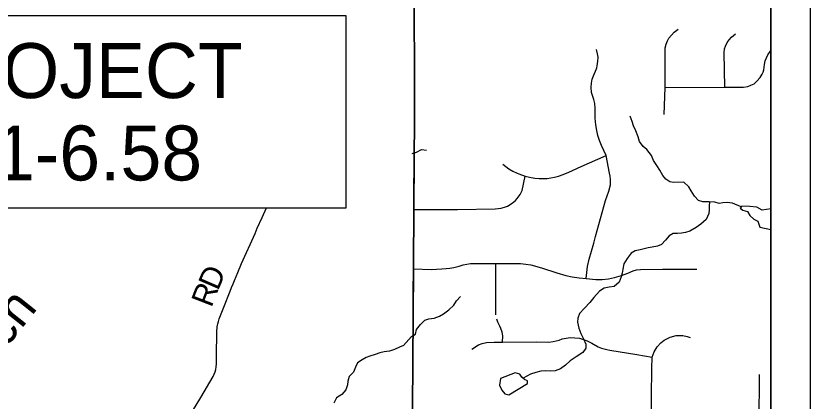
# Model space of a CAD drawing. Extents: x 0 to 34, y 0 to 22.
# Drawn here: x 6.974 to 9, y 17.051 to 18.033 of the extents above; entities that cross this region are included whole.
import ezdxf

# ---------------------------------------------------------------- set-up
doc = ezdxf.new("R2010")
doc.units = 0
for name, color, linetype in [('GM_X_Corporation', 7, 'Continuous'), ('GM_X_County_Road', 7, 'Continuous'), ('GM_X_Minor_Lake', 7, 'Continuous'), ('GM_X_Minor_River', 7, 'Continuous'), ('GM_X_Minor_River_Text', 7, 'Continuous'), ('GM_X_Township_Road', 7, 'Continuous'), ('GM_X_Township_Road_Text', 7, 'Continuous'), ('SH_Data', 7, 'Continuous'), ('SH_Text', 7, 'Continuous')]:
    doc.layers.add(name, color=color, linetype=linetype)

msp = doc.modelspace()

# ---------------------------------------------------------------- linework, layer by layer
at = {"layer": 'GM_X_Corporation'}
for points in [[(2.1, 20.9), (2.1, 14.1), (7.9734, 14.1), (7.9726, 14.5453), (7.9765, 15.2637), (7.9792, 15.5481), (7.979, 15.5988), (7.9808, 15.7192), (7.9807, 15.9078), (7.9821, 16.2487), (7.9825, 16.3395), (7.9818, 16.3982), (7.9825, 16.6077), (7.9838, 16.7968), (7.9877, 17.3871), (7.9891, 17.5498), (7.991, 17.7727), (7.9901, 18.1613)], [(7.9901, 18.1613), (7.991, 17.7727), (7.9891, 17.5498), (7.9877, 17.3871), (7.9838, 16.7968), (7.9825, 16.6077), (7.9818, 16.3982), (7.9825, 16.3395), (7.9821, 16.2487), (7.9807, 15.9078), (7.9808, 15.7192), (7.979, 15.5988), (7.9792, 15.5481), (7.9765, 15.2637), (7.9726, 14.5453), (7.9734, 14.1), (8.9, 14.1), (8.9, 20.9)], [(7.9901, 18.1613), (7.991, 17.7727), (7.9891, 17.5498), (7.9877, 17.3871), (7.9838, 16.7968), (7.9825, 16.6077), (7.9818, 16.3982), (7.9825, 16.3395), (7.9821, 16.2487), (7.9807, 15.9078), (7.9808, 15.7192), (7.979, 15.5988), (7.9792, 15.5481), (7.9765, 15.2637), (7.9726, 14.5453), (8.3169, 14.5418), (8.5518, 14.5426), (8.5844, 14.5431), (8.8409, 14.5545), (8.9, 14.5547), (8.9, 19.1229)], [(7.9901, 18.1613), (7.991, 17.7727), (7.9891, 17.5498), (7.9877, 17.3871), (7.9838, 16.7968), (7.9825, 16.6077), (7.9818, 16.3982), (7.9825, 16.3395), (7.9821, 16.2487), (7.9807, 15.9078), (7.9808, 15.7192), (7.979, 15.5988), (7.9792, 15.5481), (7.9765, 15.2637), (7.9726, 14.5453), (7.0871, 14.5429), (7.0197, 14.5427), (6.4941, 14.5412), (6.1476, 14.5397), (5.4644, 14.5374), (4.5212, 14.531)]]:
    msp.add_lwpolyline(points, dxfattribs=at)
at = {"layer": 'GM_X_County_Road'}
for points in [[(7.989, 17.539), (7.9891, 17.5666), (7.9893, 17.604), (7.9902, 17.6687), (7.9906, 17.7045), (7.9907, 17.7451), (7.9906, 17.865), (7.9905, 17.8972), (7.9906, 17.9381), (7.9907, 17.9453), (7.9907, 17.9812), (7.991, 18.0173), (7.991, 18.0579), (7.9908, 18.099), (7.9906, 18.1401), (7.991, 18.1468), (7.9921, 18.1524), (7.9937, 18.1569), (7.9963, 18.1613)], [(7.9881, 17.3883), (7.9884, 17.4416), (7.9886, 17.4756), (7.9888, 17.5096), (7.989, 17.539)], [(7.9845, 16.7972), (7.9845, 16.8156), (7.985, 16.8666), (7.9851, 16.8923), (7.9853, 16.91), (7.9857, 16.9319), (7.9859, 16.9865), (7.9861, 17.0083), (7.9861, 17.0387), (7.9865, 17.06), (7.9862, 17.0801), (7.9861, 17.1071), (7.9863, 17.1552), (7.9869, 17.2019), (7.9869, 17.2365), (7.9873, 17.288), (7.9874, 17.3067), (7.9876, 17.3377), (7.9881, 17.3757), (7.9881, 17.382), (7.9881, 17.3883)]]:
    msp.add_lwpolyline(points, dxfattribs=at)
at = {"layer": 'GM_X_Minor_Lake'}
msp.add_line((8.8721, 17.4941), (8.9, 17.4885), dxfattribs=at)
for points in [[(8.9, 17.5406), (8.8778, 17.5374), (8.8644, 17.5449), (8.8466, 17.547), (8.8261, 17.5476), (8.8212, 17.5426), (8.8284, 17.5373), (8.8399, 17.5344), (8.846, 17.5235), (8.8567, 17.5148), (8.8666, 17.5096), (8.8721, 17.4941)], [(8.21, 17.1083), (8.2075, 17.0916), (8.2137, 17.0783), (8.2213, 17.0697), (8.2312, 17.0671), (8.2788, 17.0953), (8.2787, 17.1025), (8.2711, 17.1058), (8.2646, 17.1119), (8.2596, 17.1194), (8.2474, 17.1227)], [(8.2474, 17.1227), (8.21, 17.1083)]]:
    msp.add_lwpolyline(points, dxfattribs=at)
at = {"layer": 'GM_X_Minor_River'}
for points in [[(8.8241, 17.5456), (8.8017, 17.555), (8.788, 17.5567), (8.7774, 17.5559), (8.7676, 17.5546), (8.7565, 17.5576), (8.7425, 17.559), (8.7265, 17.5588), (8.7151, 17.5625), (8.7048, 17.573), (8.6963, 17.587), (8.6909, 17.5972), (8.6775, 17.6085), (8.6513, 17.6082), (8.6418, 17.6097), (8.6315, 17.6164), (8.6239, 17.6262), (8.6165, 17.6394), (8.6088, 17.6515), (8.6, 17.6644), (8.5953, 17.6769), (8.5834, 17.6923), (8.5739, 17.7002), (8.5643, 17.7127), (8.5611, 17.7248), (8.5553, 17.7399), (8.5495, 17.7528), (8.546, 17.7638), (8.5405, 17.777)], [(7.9844, 17.6822), (7.9953, 17.6853), (8.0081, 17.6926), (8.021, 17.6901)], [(8.7433, 17.5589), (8.7426, 17.5479), (8.7423, 17.5384), (8.7416, 17.5289), (8.7345, 17.5137), (8.7214, 17.5018), (8.7093, 17.4937), (8.6927, 17.484), (8.6817, 17.4805), (8.6719, 17.4789), (8.662, 17.4784), (8.6506, 17.4779), (8.6408, 17.4725), (8.6314, 17.4614), (8.6209, 17.4499), (8.6103, 17.4456), (8.5974, 17.4432), (8.5872, 17.4416), (8.577, 17.4392), (8.566, 17.4365), (8.5539, 17.4341), (8.5437, 17.4283), (8.5328, 17.4145), (8.5246, 17.4008), (8.5224, 17.3874), (8.5206, 17.3768), (8.518, 17.3673), (8.5132, 17.3543), (8.4997, 17.3428), (8.4875, 17.3415), (8.4747, 17.3387), (8.4622, 17.3314), (8.4479, 17.3146), (8.4382, 17.3023), (8.4243, 17.2881), (8.4115, 17.2739), (8.4074, 17.2625), (8.4068, 17.2519), (8.4099, 17.2367), (8.4146, 17.2234), (8.4216, 17.2095), (8.4278, 17.1955), (8.4275, 17.186), (8.42, 17.1745), (8.4034, 17.1637), (8.3875, 17.1533), (8.3759, 17.1422), (8.3631, 17.1329), (8.3491, 17.1282), (8.3377, 17.1274), (8.3248, 17.1276), (8.3126, 17.1267), (8.2998, 17.124), (8.2869, 17.1193), (8.2678, 17.1089)], [(7.9827, 17.2153), (7.9934, 17.221), (7.9956, 17.2332), (8.0061, 17.2462), (8.0166, 17.2569), (8.0276, 17.2601), (8.0405, 17.2621), (8.0548, 17.2675), (8.0647, 17.2733), (8.0782, 17.2833), (8.0906, 17.2956), (8.0981, 17.3063), (8.1083, 17.3174)], [(7.9826, 17.2153), (7.9626, 17.1921), (7.9523, 17.1883), (7.9398, 17.1819), (7.9269, 17.1784), (7.9132, 17.1761), (7.9021, 17.1734), (7.89, 17.1696), (7.8767, 17.165), (7.8672, 17.1616), (7.8569, 17.1563), (7.8455, 17.1487), (7.8398, 17.1372), (7.8349, 17.1243), (7.8239, 17.1133), (7.8204, 17.1015), (7.8197, 17.092), (7.8155, 17.0798), (7.8049, 17.068), (7.7916, 17.0588), (7.7851, 17.0459)]]:
    msp.add_lwpolyline(points, dxfattribs=at)
at = {"layer": 'GM_X_Township_Road'}
msp.add_line((8.1981, 17.2709), (8.1981, 17.4014), dxfattribs=at)
for points in [[(8.6275, 17.7812), (8.6302, 17.8503), (8.63, 17.9512), (8.6323, 17.9609), (8.636, 17.9694), (8.6399, 17.9763), (8.6461, 17.9837), (8.6533, 17.991), (8.6632, 17.9991)], [(8.7823, 17.8514), (8.7804, 17.9388), (8.7818, 17.9487), (8.7841, 17.956), (8.7885, 17.9646), (8.7931, 17.9715), (8.7998, 17.9788), (8.8095, 17.9874)], [(8.4794, 17.6769), (8.4681, 17.702), (8.4629, 17.7151), (8.4587, 17.7281), (8.4556, 17.7408), (8.4532, 17.7554), (8.4518, 17.772), (8.4516, 17.7859), (8.4515, 17.7972), (8.4504, 17.8097), (8.4481, 17.8194), (8.4448, 17.83), (8.4424, 17.8375), (8.4415, 17.8508), (8.4421, 17.8611), (8.4438, 17.8715), (8.4473, 17.88), (8.4521, 17.8919), (8.4554, 17.9006), (8.4568, 17.9058), (8.4587, 17.9172), (8.4589, 17.9274), (8.4579, 17.9362), (8.4551, 17.9475)], [(8.6302, 17.8503), (8.7823, 17.8514), (8.83, 17.8514), (8.8408, 17.8528), (8.8488, 17.8563), (8.8571, 17.86), (8.8643, 17.8662), (8.8726, 17.8754), (8.8774, 17.8839), (8.8804, 17.8892), (8.8817, 17.8955), (8.8836, 17.909), (8.8855, 17.9178), (8.8885, 17.9256), (8.8919, 17.9332), (8.8977, 17.942), (8.9, 17.9451)], [(8.2162, 17.655), (8.2237, 17.6489), (8.2317, 17.6433), (8.2418, 17.6371), (8.2526, 17.6317), (8.2564, 17.63), (8.2731, 17.6241), (8.2843, 17.6213), (8.2974, 17.6191), (8.3083, 17.6182), (8.3171, 17.618), (8.329, 17.6186), (8.3383, 17.6198), (8.3482, 17.6216), (8.3577, 17.624), (8.3701, 17.6282), (8.3847, 17.6346), (8.416, 17.6485), (8.4794, 17.6769)], [(8.4283, 17.3634), (8.4322, 17.3939), (8.4359, 17.4123), (8.4478, 17.4533), (8.4527, 17.4701), (8.4781, 17.5623), (8.4866, 17.5862), (8.4904, 17.6019), (8.491, 17.6094), (8.4908, 17.6153), (8.4898, 17.6238), (8.4878, 17.6318), (8.4794, 17.6769)], [(7.989, 17.539), (8.1001, 17.539), (8.1961, 17.5407), (8.2117, 17.5425), (8.2226, 17.5459), (8.2277, 17.5481), (8.2398, 17.5553), (8.2482, 17.5623), (8.2527, 17.567), (8.2603, 17.5775), (8.2656, 17.5879), (8.2731, 17.6241)], [(7.4245, 17.0249), (7.4454, 17.0598), (7.4766, 17.1133), (7.4794, 17.1192), (7.482, 17.1257), (7.4837, 17.1316), (7.4846, 17.1379), (7.4853, 17.146), (7.4858, 17.1743), (7.4862, 17.2182), (7.4864, 17.2267), (7.4866, 17.2313), (7.4871, 17.236), (7.4875, 17.2402), (7.4882, 17.2442), (7.4889, 17.2479), (7.4902, 17.2534), (7.4915, 17.2574), (7.4926, 17.2605), (7.5043, 17.2904), (7.5199, 17.3308), (7.5237, 17.3405), (7.5277, 17.3501), (7.5311, 17.358), (7.54, 17.379), (7.5496, 17.4014), (7.5838, 17.4782), (7.5896, 17.4915), (7.602, 17.5191), (7.6127, 17.5433)], [(7.9881, 17.3883), (8.0332, 17.386), (8.0601, 17.3881), (8.0712, 17.3887), (8.0809, 17.3893), (8.0909, 17.3911), (8.1045, 17.3951), (8.115, 17.3981), (8.1238, 17.4002), (8.1332, 17.4014), (8.1981, 17.4014), (8.2477, 17.4017), (8.2609, 17.4014), (8.2745, 17.4002), (8.2872, 17.3981), (8.3144, 17.3905), (8.354, 17.3775), (8.3766, 17.3706), (8.393, 17.3673), (8.4108, 17.3651), (8.4283, 17.3634), (8.4531, 17.3609), (8.4697, 17.3609), (8.4857, 17.3627), (8.5005, 17.3661), (8.5189, 17.3709), (8.5352, 17.3769), (8.5482, 17.3827), (8.5567, 17.3854), (8.5675, 17.3866), (8.6231, 17.3869), (8.711, 17.3869)], [(8.2151, 17.2006), (8.2159, 17.2174), (8.2144, 17.2268), (8.2111, 17.2359), (8.2081, 17.2416), (8.2029, 17.2518), (8.2006, 17.2594)], [(8.1365, 17.1835), (8.1536, 17.1942), (8.1633, 17.1978), (8.174, 17.2003), (8.1937, 17.201), (8.2151, 17.2006), (8.3026, 17.2016), (8.3337, 17.201), (8.3445, 17.2024), (8.3598, 17.206), (8.3677, 17.2096), (8.3773, 17.2115), (8.3881, 17.2128), (8.3996, 17.2124), (8.4116, 17.211), (8.422, 17.2082), (8.4314, 17.2046), (8.4431, 17.1985), (8.4588, 17.1892), (8.4681, 17.1853), (8.481, 17.182), (8.489, 17.1808), (8.5578, 17.1692), (8.5973, 17.1627)], [(8.5955, 17.018), (8.5952, 17.0623), (8.5962, 17.1341), (8.5973, 17.1627), (8.6024, 17.1764), (8.6099, 17.1893), (8.6194, 17.1995), (8.6279, 17.206), (8.6429, 17.2138), (8.6585, 17.2179), (8.6756, 17.2179), (8.6865, 17.2155), (8.6943, 17.2128)], [(8.9, 16.9151), (8.8998, 16.9152), (8.8905, 16.9226), (8.8848, 16.9283), (8.8813, 16.9333), (8.8749, 16.9447), (8.8717, 16.9539), (8.8698, 16.962), (8.8694, 16.97), (8.87, 16.9799), (8.8703, 16.9945), (8.871, 17.1184)]]:
    msp.add_lwpolyline(points, dxfattribs=at)
at = {"layer": 'SH_Data'}
for p, q in [((9, 21), (9, 14)), ((8.9, 20.9), (8.9, 14.1))]:
    msp.add_line(p, q, dxfattribs=at)
at = {"layer": 'SH_Text'}
msp.add_lwpolyline([(6.1613, 17.5433), (7.8161, 17.5433), (7.8161, 18.0333), (6.1613, 18.0333)], close=True, dxfattribs=at)

# ---------------------------------------------------------------- texts
at = {"layer": 'GM_X_Minor_River_Text'}
msp.add_text('Ditch', height=0.09474, rotation=51.42, dxfattribs=at).set_placement((6.851, 17.0624))
at = {"layer": 'GM_X_Township_Road_Text'}
for s, rotation, p in [('D', 66.6101, (7.489, 17.3304)), ('R', 68.8661, (7.4724, 17.2874))]:
    msp.add_text(s, height=0.0568, rotation=rotation, dxfattribs=at).set_placement(p)
at = {"layer": 'SH_Text'}
for s, p in [('END PROJECT', (6.2313, 17.8233)), ('MED-271-6.58', (6.2313, 17.6133))]:
    msp.add_text(s, height=0.14, dxfattribs=at).set_placement(p)

doc.saveas('drawing.dxf')
